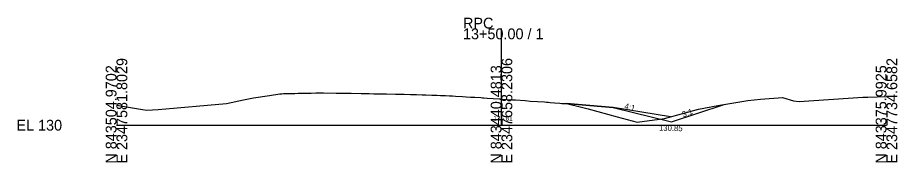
# Model space of a CAD drawing. Extents: x -26 to 203, y -10 to 7538.
# Drawn here: x -25.7 to 202.8, y -9.7 to 28 of the extents above; entities that cross this region are included whole.
import ezdxf

# ---------------------------------------------------------------- set-up
doc = ezdxf.new("R2010")
doc.units = 0
for name, color, linetype in [('Exist Cross Section Cell', 7, 'Continuous'), ('Exist XS Center Line Elevation Label', 7, 'Continuous'), ('Exist XS Ground Line', 7, 'Continuous'), ('Prop CMT Slope Grass', 7, 'Continuous'), ('Prop XS Earthwork Shape', 7, 'Continuous'), ('Prop XS SE Text', 7, 'Continuous')]:
    doc.layers.add(name, color=color, linetype=linetype)

msp = doc.modelspace()

# ---------------------------------------------------------------- linework, layer by layer
at = {"layer": 'Exist Cross Section Cell'}
for p, q in [((100, 0), (100, 25.17)), ((0, 0), (100, 0)), ((100, 0), (200, 0))]:
    msp.add_line(p, q, dxfattribs=at)
at = {"layer": 'Exist XS Ground Line'}
msp.add_lwpolyline([(0, 5.18), (6.74, 4.06), (7.9, 3.87), (10.85, 4.12), (28.57, 5.62), (32.97, 6.57), (35.58, 7.1), (39.75, 7.75), (42.43, 8.18), (42.92, 8.19), (43.37, 8.21), (44.62, 8.25), (45.42, 8.27), (46.36, 8.29), (47.22, 8.31), (48.2, 8.33), (49.3, 8.35), (49.97, 8.36), (50.54, 8.37), (51.75, 8.38), (53.32, 8.38), (53.78, 8.39), (57.09, 8.37), (58.79, 8.35), (60.35, 8.32), (60.65, 8.32), (60.98, 8.31), (63.53, 8.27), (64.48, 8.25), (65.65, 8.22), (66.85, 8.2), (67.66, 8.18), (68.64, 8.16), (70.1, 8.14), (72.51, 8.09), (72.94, 8.08), (73.31, 8.07), (74.75, 8.04), (76.39, 8.01), (76.7, 8), (77.93, 7.96), (79.42, 7.91), (80.31, 7.89), (81.92, 7.83), (83.23, 7.79), (84.2, 7.75), (85.45, 7.69), (86.53, 7.64), (87.27, 7.6), (88.08, 7.55), (89.83, 7.45), (90.79, 7.4), (91.96, 7.33), (93.07, 7.26), (94.65, 7.18), (95.07, 7.16), (95.39, 7.13), (96.31, 7.06), (97.86, 6.95), (99.66, 6.84), (100, 6.81), (102.84, 6.62), (103.19, 6.59), (103.62, 6.56), (106.11, 6.39), (107.44, 6.29), (109.35, 6.16), (111.21, 6.04), (111.66, 6.02), (112.15, 5.97), (112.61, 5.91), (113.77, 5.83), (115.19, 5.72), (115.69, 5.68), (116.29, 5.65), (116.87, 5.61), (120.78, 4.65), (122.55, 4.28), (130.09, 2.2), (135.28, 0.79), (142.34, 1.7), (151.14, 4.2), (156.18, 5.13), (164, 6.45), (167.29, 6.74), (172.96, 7.17), (175.85, 6.38), (177.29, 6.17), (193.84, 7.29), (195.16, 7.32), (200, 7.44)], dxfattribs=at)
at = {"layer": 'Prop CMT Slope Grass'}
msp.add_line((116.87, 5.61), (129, 4.64), dxfattribs=at)
for points in [[(129, 4.64), (144.16, 0.85)], [(144.16, 0.85), (157.81, 5.4)]]:
    msp.add_lwpolyline(points, dxfattribs=at)
at = {"layer": 'Prop XS Earthwork Shape'}
msp.add_lwpolyline([(142.34, 1.7), (143.93, 2.15), (129, 4.64), (116.87, 5.61), (120.78, 4.65), (122.55, 4.28), (130.09, 2.2), (135.28, 0.79)], close=True, dxfattribs=at)

# ---------------------------------------------------------------- texts
at = {"layer": 'Exist Cross Section Cell'}
for s, p in [('RPC', (90, 25.17)), ('13+50.00 / 1', (90, 22.37)), ('EL 130', (-26, -1.4))]:
    msp.add_text(s, height=2.8, dxfattribs=at).set_placement(p)
for s, p in [('E 2347581.8029', (2.8, -10)), ('E 2347658.2306', (102.8, -10)), ('E 2347734.6582', (202.8, -10)), ('N 843504.9702', (0, -10)), ('N 843440.4813', (100, -10)), ('N 843375.9925', (200, -10))]:
    msp.add_text(s, height=2.8, rotation=90, dxfattribs=at).set_placement(p)
at = {"layer": 'Exist XS Center Line Elevation Label'}
msp.add_text('136.81', height=1.2, dxfattribs=at).set_placement((97.86, 1.21))
at = {"layer": 'Prop XS SE Text'}
for s, rotation, p in [('4:1', 345.0323, (131.81, 4.35)), ('3:1', 19.2891, (147.21, 2.03)), ('130.85', 358.5679, (140.89, -1.42))]:
    msp.add_text(s, height=1.5, rotation=rotation, dxfattribs=at).set_placement(p)

doc.saveas('drawing.dxf')
